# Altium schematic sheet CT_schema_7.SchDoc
size 411 x 402 mm
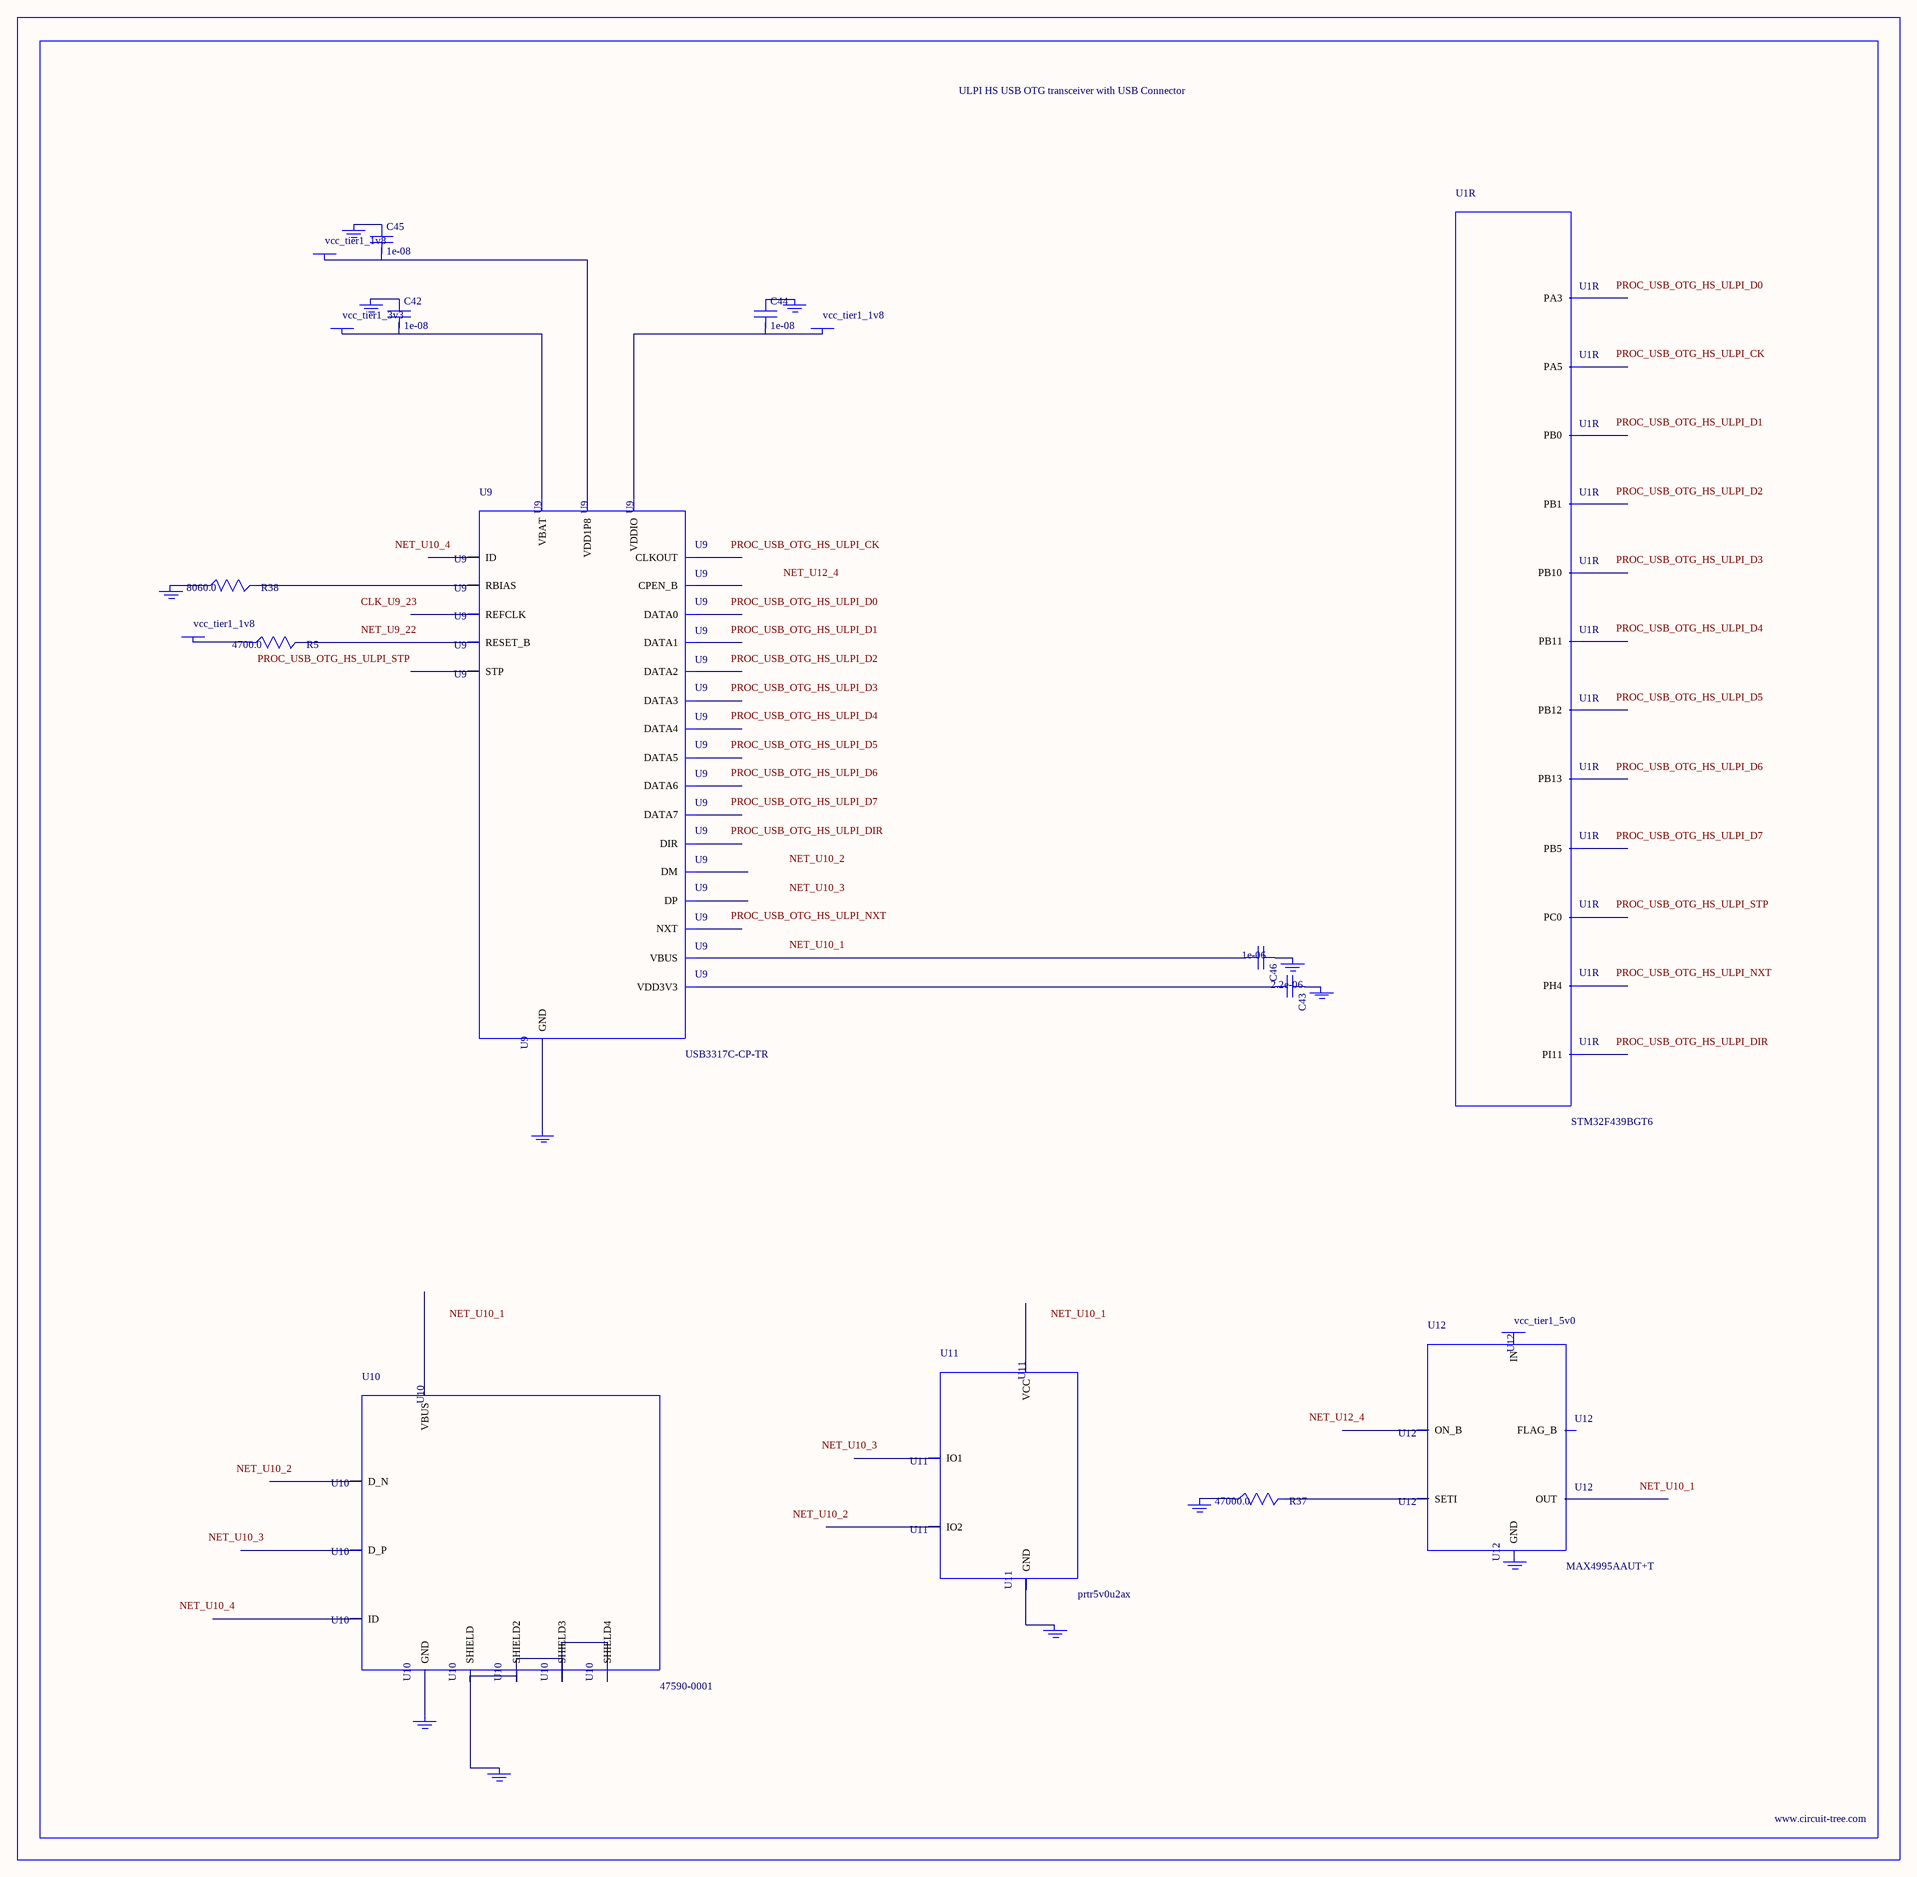
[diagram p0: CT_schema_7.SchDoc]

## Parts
BORDER6  (no value)
C42  1e-08  [C0402]
C43  2.2e-06  [C0603]
C44  1e-08  [C0402]
C45  1e-08  [C0402]
C46  1e-06  [C0603]
GND_INSTANCE_6_0  (no value)
GND_INSTANCE_6_1  (no value)
GND_INSTANCE_6_2  (no value)
GND_INSTANCE_6_3  (no value)
GND_INSTANCE_6_4  (no value)
GND_INSTANCE_6_5  (no value)
GND_INSTANCE_6_6  (no value)
GND_INSTANCE_6_7  (no value)
GND_INSTANCE_6_8  (no value)
GND_INSTANCE_6_9  (no value)
GND_INSTANCE_6_10  (no value)
GND_INSTANCE_6_11  (no value)
POWER_INSTANCE_6_0  vcc_tier1_3v3
POWER_INSTANCE_6_1  vcc_tier1_1v8
POWER_INSTANCE_6_2  vcc_tier1_1v8
POWER_INSTANCE_6_3  vcc_tier1_1v8
POWER_INSTANCE_6_4  vcc_tier1_5v0
R5  4700.0  [R0603]
R37  47000.0  [R0603]
R38  8060.0  [R0603]
U1  STM32F439BGT6  [LQFP208]  (part R of 18)
U9  USB3317C-CP-TR  [QFN-24]
U10  47590-0001  [MICRO_USB_AB]
U11  prtr5v0u2ax  [SOT143B]
U12  MAX4995AAUT+T  [SOT-23-6]

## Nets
NetC42_1: C42.1 GND_INSTANCE_6_1.0(GND)
NetC42_2: C42.2 POWER_INSTANCE_6_0.0(PWR) U9.3(VBAT)
NetC43_1: C43.1 GND_INSTANCE_6_2.0(GND)
NetC43_2: C43.2 U9.4(VDD3V3)
NetC44_1: C44.1 GND_INSTANCE_6_3.0(GND)
NetC44_2: C44.2 POWER_INSTANCE_6_1.0(PWR) U9.17(VDDIO)
NetC45_1: C45.1 GND_INSTANCE_6_4.0(GND)
NetC45_2: C45.2 POWER_INSTANCE_6_2.0(PWR) U9.21(VDD1P8)
NetC46_1: C46.1 GND_INSTANCE_6_0.0(GND)
NetC46_2: C46.2 U9.2(VBUS)
NetGND_INSTANCE_6_5_0: GND_INSTANCE_6_5.0(GND) R38.1
NetGND_INSTANCE_6_6_0: GND_INSTANCE_6_6.0(GND) U9.25(GND)
NetGND_INSTANCE_6_7_0: GND_INSTANCE_6_7.0(GND) U10.6(SHIELD) U10.7(SHIELD2) U10.8(SHIELD3) U10.9(SHIELD4)
NetGND_INSTANCE_6_8_0: GND_INSTANCE_6_8.0(GND) U10.5(GND)
NetGND_INSTANCE_6_9_0: GND_INSTANCE_6_9.0(GND) U11.1(GND)
NetGND_INSTANCE_6_10_0: GND_INSTANCE_6_10.0(GND) R37.1
NetPOWER_INSTANCE_6_3_0: POWER_INSTANCE_6_3.0(PWR) R5.1
NetR5_2: R5.2 U9.22(RESET_B)
NetR37_2: R37.2 U12.3(SETI)
NetR38_2: R38.2 U9.24(RBIAS)

Not connected (* = marked no-connect by the designer): GND_INSTANCE_6_11 0(GND); POWER_INSTANCE_6_4 0(PWR); U1 13(PI11) 35(PC0) 48(PH4) 50(PA3) 54(PA5) 61(PB0) 62(PB1) 90(PB10) 91(PB11) 104(PB12) 105(PB13) 194(PB5); U9 1(ID) 5(DM) 6(DP) 7(CPEN_B) 8(DATA7) 9(DATA6) 10(DATA5) 11(DATA4) 12(CLKOUT) 13(DATA3) 14(DATA2) 15(DATA1) 16(DATA0) 18(NXT) 19(DIR) 20(STP) 23(REFCLK); U10 1(VBUS) 2(D_N) 3(D_P) 4(ID); U11 2(IO1) 3(IO2) 4(VCC); U12 1(OUT) 2(GND) 4(ON_B) 5(IN) 6(FLAG_B)

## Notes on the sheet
- Labels drawn without touching a wire or pin: CLK_U9_23, NET_U9_22, NET_U10_1, NET_U10_2, NET_U10_3, NET_U10_4, NET_U12_4, PROC_USB_OTG_HS_ULPI_CK, PROC_USB_OTG_HS_ULPI_D0, PROC_USB_OTG_HS_ULPI_D1, PROC_USB_OTG_HS_ULPI_D2, PROC_USB_OTG_HS_ULPI_D3, PROC_USB_OTG_HS_ULPI_D4, PROC_USB_OTG_HS_ULPI_D5, PROC_USB_OTG_HS_ULPI_D6, PROC_USB_OTG_HS_ULPI_D7, PROC_USB_OTG_HS_ULPI_DIR, PROC_USB_OTG_HS_ULPI_NXT, PROC_USB_OTG_HS_ULPI_STP

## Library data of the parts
BORDER6 = BORDER_PAGE6
C42 C44 C45 = C0402C103K3RAC
C43 = C0603C225K8RACTU
C46 = C0603C105K3RACTU
GND_INSTANCE_6_0-GND_INSTANCE_6_11 = GND
POWER_INSTANCE_6_0-POWER_INSTANCE_6_4 = PWR
R5 = RC0603JR-074K7L
R37 = RC0603JR-0747KL
R38 = ERJ-3EKF8061V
